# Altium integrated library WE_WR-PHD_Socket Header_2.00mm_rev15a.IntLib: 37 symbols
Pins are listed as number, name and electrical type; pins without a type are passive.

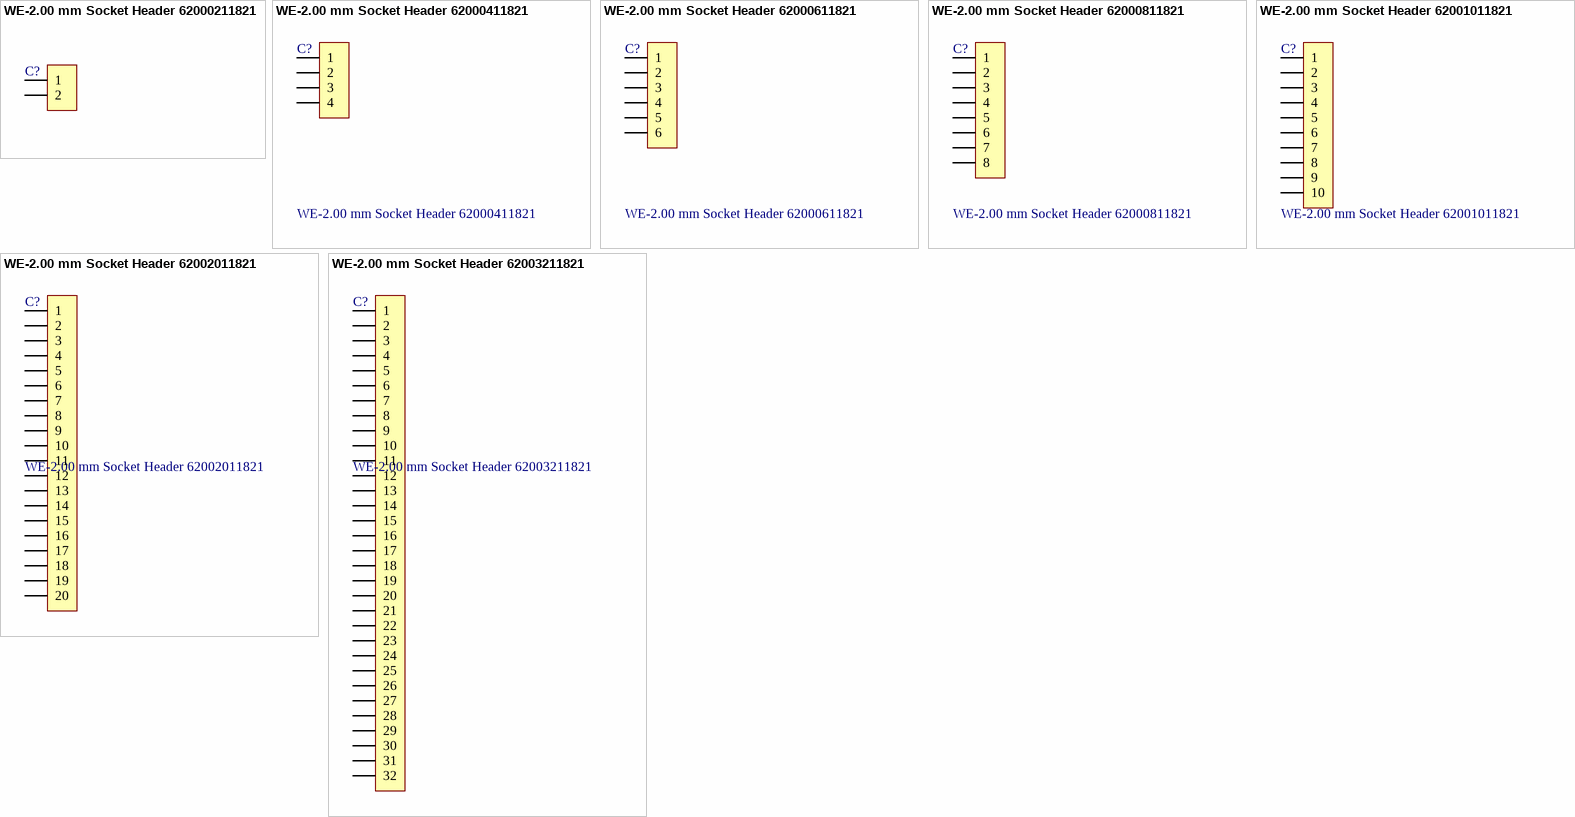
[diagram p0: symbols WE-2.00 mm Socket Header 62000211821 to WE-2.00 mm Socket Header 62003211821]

## WE-2.00 mm Socket Header 62000211821
designator C?
WR-PHD 2.00 mm Socket Header; Manufacturer: Würth Elektronik eiSos GmbH; ComponentLink1 Description: Manufacturer; ComponentLink2 Description: Datasheet; NoPins: 02
footprint 62000211821 (2p, 1 row, straight, gold plating)
pins: 1, 2

## WE-2.00 mm Socket Header 62000411821
designator C?
WR-PHD 2.00 mm Socket Header; Manufacturer: Würth Elektronik eiSos GmbH; ComponentLink1 Description: Manufacturer; ComponentLink2 Description: Datasheet; NoPins: 04
footprint 62000411821 (4p, 1 row, straight, gold plating)
pins: 1, 2, 3, 4

## WE-2.00 mm Socket Header 62000611821
designator C?
WR-PHD 2.00 mm Socket Header; Manufacturer: Würth Elektronik eiSos GmbH; ComponentLink1 Description: Manufacturer; ComponentLink2 Description: Datasheet; NoPins: 06
footprint 62000611821 (6p, 1 row, straight, gold plating)
pins: 1, 2, 3, 4, 5, 6

## WE-2.00 mm Socket Header 62000811821
designator C?
WR-PHD 2.00 mm Socket Header; Manufacturer: Würth Elektronik eiSos GmbH; ComponentLink1 Description: Manufacturer; ComponentLink2 Description: Datasheet; NoPins: 08
footprint 62000811821 (8p, 1 row, straight, gold plating)
pins: 1, 2, 3, 4, 5, 6, 7, 8

## WE-2.00 mm Socket Header 62001011821
designator C?
WR-PHD 2.00 mm Socket Header; Manufacturer: Würth Elektronik eiSos GmbH; ComponentLink1 Description: Manufacturer; ComponentLink2 Description: Datasheet; NoPins: 10
footprint 62001011821 (10p, 1 row, straight, gold plating)
pins: 1, 2, 3, 4, 5, 6, 7, 8, 9, 10

## WE-2.00 mm Socket Header 62002011821
designator C?
WR-PHD 2.00 mm Socket Header; Manufacturer: Würth Elektronik eiSos GmbH; ComponentLink1 Description: Manufacturer; ComponentLink2 Description: Datasheet; NoPins: 20
footprint 62002011821 (20p, 1 row, straight, gold plating)
pins: 1, 2, 3, 4, 5, 6, 7, 8, 9, 10, 11, 12, 13, 14, 15, 16, 17, 18, 19, 20

## WE-2.00 mm Socket Header 62003211821
designator C?
WR-PHD 2.00 mm Socket Header; Manufacturer: Würth Elektronik eiSos GmbH; ComponentLink1 Description: Manufacturer; ComponentLink2 Description: Datasheet; NoPins: 32
footprint 62003211821 (32p, 1 row, straight, gold plating)
pins: 1, 2, 3, 4, 5, 6, 7, 8, 9, 10, 11, 12, 13, 14, 15, 16, 17, 18, 19, 20, 21, 22, 23, 24, 25, 26, 27, 28, 29, 30, 31, 32


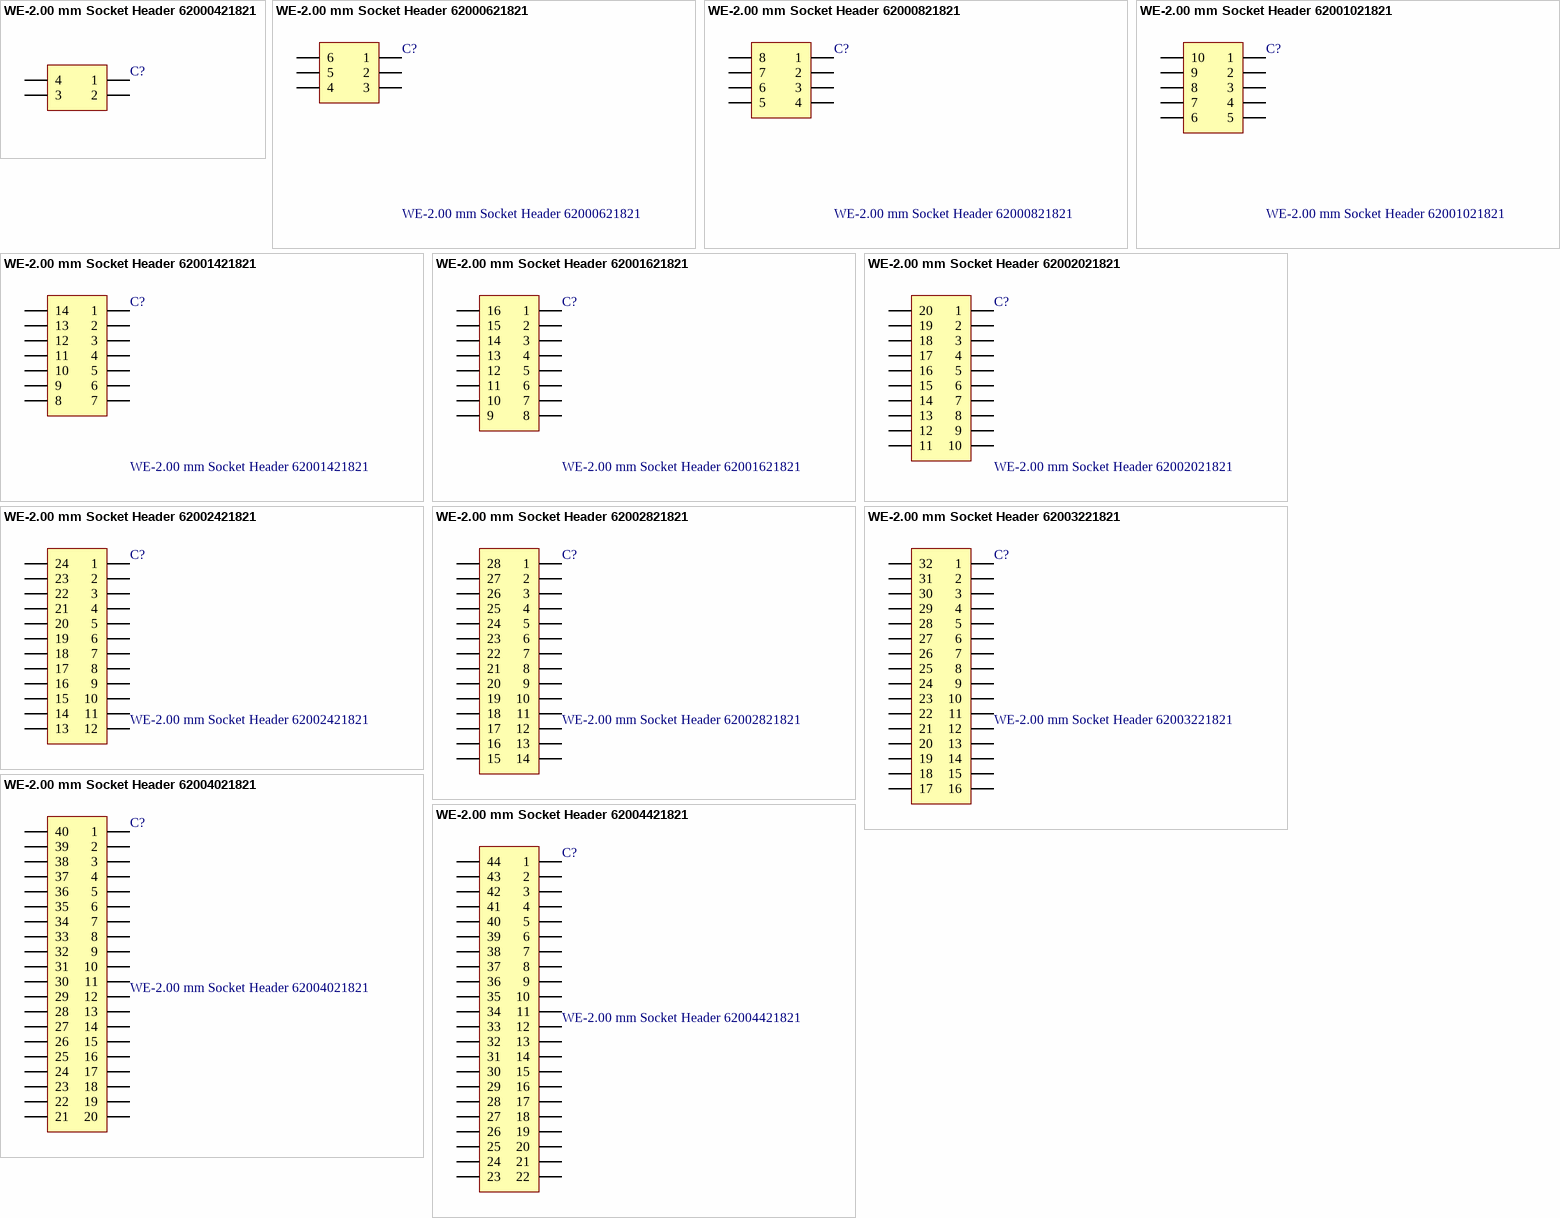
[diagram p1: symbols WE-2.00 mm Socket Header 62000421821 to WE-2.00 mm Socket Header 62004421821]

## WE-2.00 mm Socket Header 62000421821
designator C?
WR-PHD 2.00 mm Dual Socket Header; Manufacturer: Würth Elektronik eiSos GmbH; ComponentLink1 Description: Manufacturer; ComponentLink2 Description: Datasheet; NoPins: 04
footprint 62000421821 (4 pins, dual row, straight, gold plating)
pins: 1, 2, 3, 4

## WE-2.00 mm Socket Header 62000621821
designator C?
WR-PHD 2.00 mm Dual Socket Header; Manufacturer: Würth Elektronik eiSos GmbH; ComponentLink1 Description: Manufacturer; ComponentLink2 Description: Datasheet; NoPins: 06
footprint 62000621821 (6 pins, dual row, straight, gold plating)
pins: 1, 2, 3, 4, 5, 6

## WE-2.00 mm Socket Header 62000821821
designator C?
WR-PHD 2.00 mm Dual Socket Header; Manufacturer: Würth Elektronik eiSos GmbH; ComponentLink1 Description: Manufacturer; ComponentLink2 Description: Datasheet; NoPins: 08
footprint 62000821821 (8 pins, dual row, straight, gold plating)
pins: 1, 2, 3, 4, 5, 6, 7, 8

## WE-2.00 mm Socket Header 62001021821
designator C?
WR-PHD 2.00 mm Dual Socket Header; Manufacturer: Würth Elektronik eiSos GmbH; ComponentLink1 Description: Manufacturer; ComponentLink2 Description: Datasheet; NoPins: 10
footprint 62001021821 (10 pins, dual row, straight, gold plating)
pins: 1, 2, 3, 4, 5, 6, 7, 8, 9, 10

## WE-2.00 mm Socket Header 62001421821
designator C?
WR-PHD 2.00 mm Dual Socket Header; Manufacturer: Würth Elektronik eiSos GmbH; ComponentLink1 Description: Manufacturer; ComponentLink2 Description: Datasheet; NoPins: 14
footprint 62001421821 (14 pins, dual row, straight, gold plating)
pins: 1, 2, 3, 4, 5, 6, 7, 8, 9, 10, 11, 12, 13, 14

## WE-2.00 mm Socket Header 62001621821
designator C?
WR-PHD 2.00 mm Dual Socket Header; Manufacturer: Würth Elektronik eiSos GmbH; ComponentLink1 Description: Manufacturer; ComponentLink2 Description: Datasheet; NoPins: 16
footprint 62001621821 (16 pins, dual row, straight, gold plating)
pins: 1, 2, 3, 4, 5, 6, 7, 8, 9, 10, 11, 12, 13, 14, 15, 16

## WE-2.00 mm Socket Header 62002021821
designator C?
WR-PHD 2.00 mm Dual Socket Header; Manufacturer: Würth Elektronik eiSos GmbH; ComponentLink1 Description: Manufacturer; ComponentLink2 Description: Datasheet; NoPins: 20
footprint 62002021821 (20 pins, dual row, straight, gold plating)
pins: 1, 2, 3, 4, 5, 6, 7, 8, 9, 10, 11, 12, 13, 14, 15, 16, 17, 18, 19, 20

## WE-2.00 mm Socket Header 62002421821
designator C?
WR-PHD 2.00 mm Dual Socket Header; Manufacturer: Würth Elektronik eiSos GmbH; ComponentLink1 Description: Manufacturer; ComponentLink2 Description: Datasheet; NoPins: 24
footprint 62002421821 (24 pins, dual row, straight, gold plating)
pins: 1, 2, 3, 4, 5, 6, 7, 8, 9, 10, 11, 12, 13, 14, 15, 16, 17, 18, 19, 20, 21, 22, 23, 24

## WE-2.00 mm Socket Header 62002821821
designator C?
WR-PHD 2.00 mm Dual Socket Header; Manufacturer: Würth Elektronik eiSos GmbH; ComponentLink1 Description: Manufacturer; ComponentLink2 Description: Datasheet; NoPins: 28
footprint 62002821821 (28 pins, dual row, straight, gold plating)
pins: 1, 2, 3, 4, 5, 6, 7, 8, 9, 10, 11, 12, 13, 14, 15, 16, 17, 18, 19, 20, 21, 22, 23, 24, 25, 26, 27, 28

## WE-2.00 mm Socket Header 62003221821
designator C?
WR-PHD 2.00 mm Dual Socket Header; Manufacturer: Würth Elektronik eiSos GmbH; ComponentLink1 Description: Manufacturer; ComponentLink2 Description: Datasheet; NoPins: 32
footprint 62003221821 (32 pins, dual row, straight, gold plating)
pins: 1, 2, 3, 4, 5, 6, 7, 8, 9, 10, 11, 12, 13, 14, 15, 16, 17, 18, 19, 20, 21, 22, 23, 24, 25, 26, 27, 28, 29, 30, 31, 32

## WE-2.00 mm Socket Header 62004021821
designator C?
WR-PHD 2.00 mm Dual Socket Header; Manufacturer: Würth Elektronik eiSos GmbH; ComponentLink1 Description: Manufacturer; ComponentLink2 Description: Datasheet; NoPins: 40
footprint 62004021821 (40 pins, dual row, straight, gold plating)
pins: 1, 2, 3, 4, 5, 6, 7, 8, 9, 10, 11, 12, 13, 14, 15, 16, 17, 18, 19, 20, 21, 22, 23, 24, 25, 26, 27, 28, 29, 30, 31, 32, 33, 34, 35, 36, 37, 38, 39, 40

## WE-2.00 mm Socket Header 62004421821
designator C?
WR-PHD 2.00 mm Dual Socket Header; Manufacturer: Würth Elektronik eiSos GmbH; ComponentLink1 Description: Manufacturer; ComponentLink2 Description: Datasheet; NoPins: 44
footprint 62004421821 (44 pins, dual row, straight, gold plating)
pins: 1, 2, 3, 4, 5, 6, 7, 8, 9, 10, 11, 12, 13, 14, 15, 16, 17, 18, 19, 20, 21, 22, 23, 24, 25, 26, 27, 28, 29, 30, 31, 32, 33, 34, 35, 36, 37, 38, 39, 40, 41, 42, 43, 44


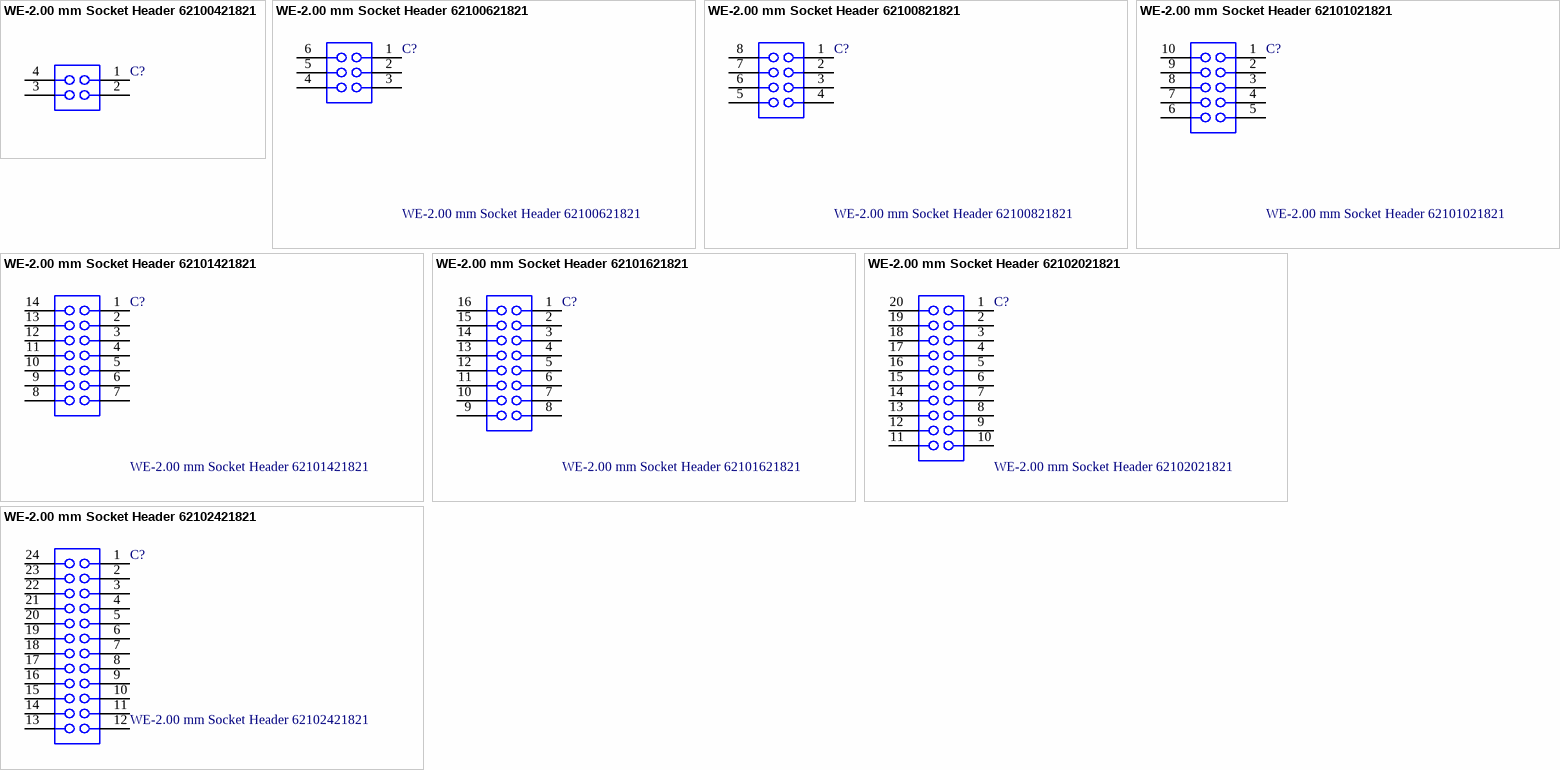
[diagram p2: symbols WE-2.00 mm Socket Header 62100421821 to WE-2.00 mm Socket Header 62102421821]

## WE-2.00 mm Socket Header 62100421821
designator C?
WR-PHD 2.00 mm Dual SMT Socket Header; Manufacturer: Würth Elektronik eiSos GmbH; ComponentLink1 Description: Manufacturer; ComponentLink2 Description: Datasheet; NoPins: 04
footprint 62100421821 (4 pins, dual row, straight, gold plating)
pins: 1, 2, 3, 4

## WE-2.00 mm Socket Header 62100621821
designator C?
WR-PHD 2.00 mm Dual SMT Socket Header; Manufacturer: Würth Elektronik eiSos GmbH; ComponentLink1 Description: Manufacturer; ComponentLink2 Description: Datasheet; NoPins: 06
footprint 62100621821 (6 pins, dual row, straight, gold plating)
pins: 1, 2, 3, 4, 5, 6

## WE-2.00 mm Socket Header 62100821821
designator C?
WR-PHD 2.00 mm Dual SMT Socket Header; Manufacturer: Würth Elektronik eiSos GmbH; ComponentLink1 Description: Manufacturer; ComponentLink2 Description: Datasheet; NoPins: 08
footprint 62100821821 (8 pins, dual row, straight, gold plating)
pins: 1, 2, 3, 4, 5, 6, 7, 8

## WE-2.00 mm Socket Header 62101021821
designator C?
WR-PHD 2.00 mm Dual SMT Socket Header; Manufacturer: Würth Elektronik eiSos GmbH; ComponentLink1 Description: Manufacturer; ComponentLink2 Description: Datasheet; NoPins: 10
footprint 62101021821 (10 pins, dual row, straight, gold plating)
pins: 1, 2, 3, 4, 5, 6, 7, 8, 9, 10

## WE-2.00 mm Socket Header 62101421821
designator C?
WR-PHD 2.00 mm Dual SMT Socket Header; Manufacturer: Würth Elektronik eiSos GmbH; ComponentLink1 Description: Manufacturer; ComponentLink2 Description: Datasheet; NoPins: 14
footprint 62101421821 (14 pins, dual row, straight, gold plating)
pins: 1, 2, 3, 4, 5, 6, 7, 8, 9, 10, 11, 12, 13, 14

## WE-2.00 mm Socket Header 62101621821
designator C?
WR-PHD 2.00 mm Dual SMT Socket Header; Manufacturer: Würth Elektronik eiSos GmbH; ComponentLink1 Description: Manufacturer; ComponentLink2 Description: Datasheet; NoPins: 16
footprint 62101621821 (16 pins, dual row, straight, gold plating)
pins: 1, 2, 3, 4, 5, 6, 7, 8, 9, 10, 11, 12, 13, 14, 15, 16

## WE-2.00 mm Socket Header 62102021821
designator C?
WR-PHD 2.00 mm Dual SMT Socket Header; Manufacturer: Würth Elektronik eiSos GmbH; ComponentLink1 Description: Manufacturer; ComponentLink2 Description: Datasheet; NoPins: 20
footprint 62102021821 (20 pins, dual row, straight, gold plating)
pins: 1, 2, 3, 4, 5, 6, 7, 8, 9, 10, 11, 12, 13, 14, 15, 16, 17, 18, 19, 20

## WE-2.00 mm Socket Header 62102421821
designator C?
WR-PHD 2.00 mm Dual SMT Socket Header; Manufacturer: Würth Elektronik eiSos GmbH; ComponentLink1 Description: Manufacturer; ComponentLink2 Description: Datasheet; NoPins: 24
footprint 62102421821 (24 pins, dual row, straight, gold plating)
pins: 1, 2, 3, 4, 5, 6, 7, 8, 9, 10, 11, 12, 13, 14, 15, 16, 17, 18, 19, 20, 21, 22, 23, 24


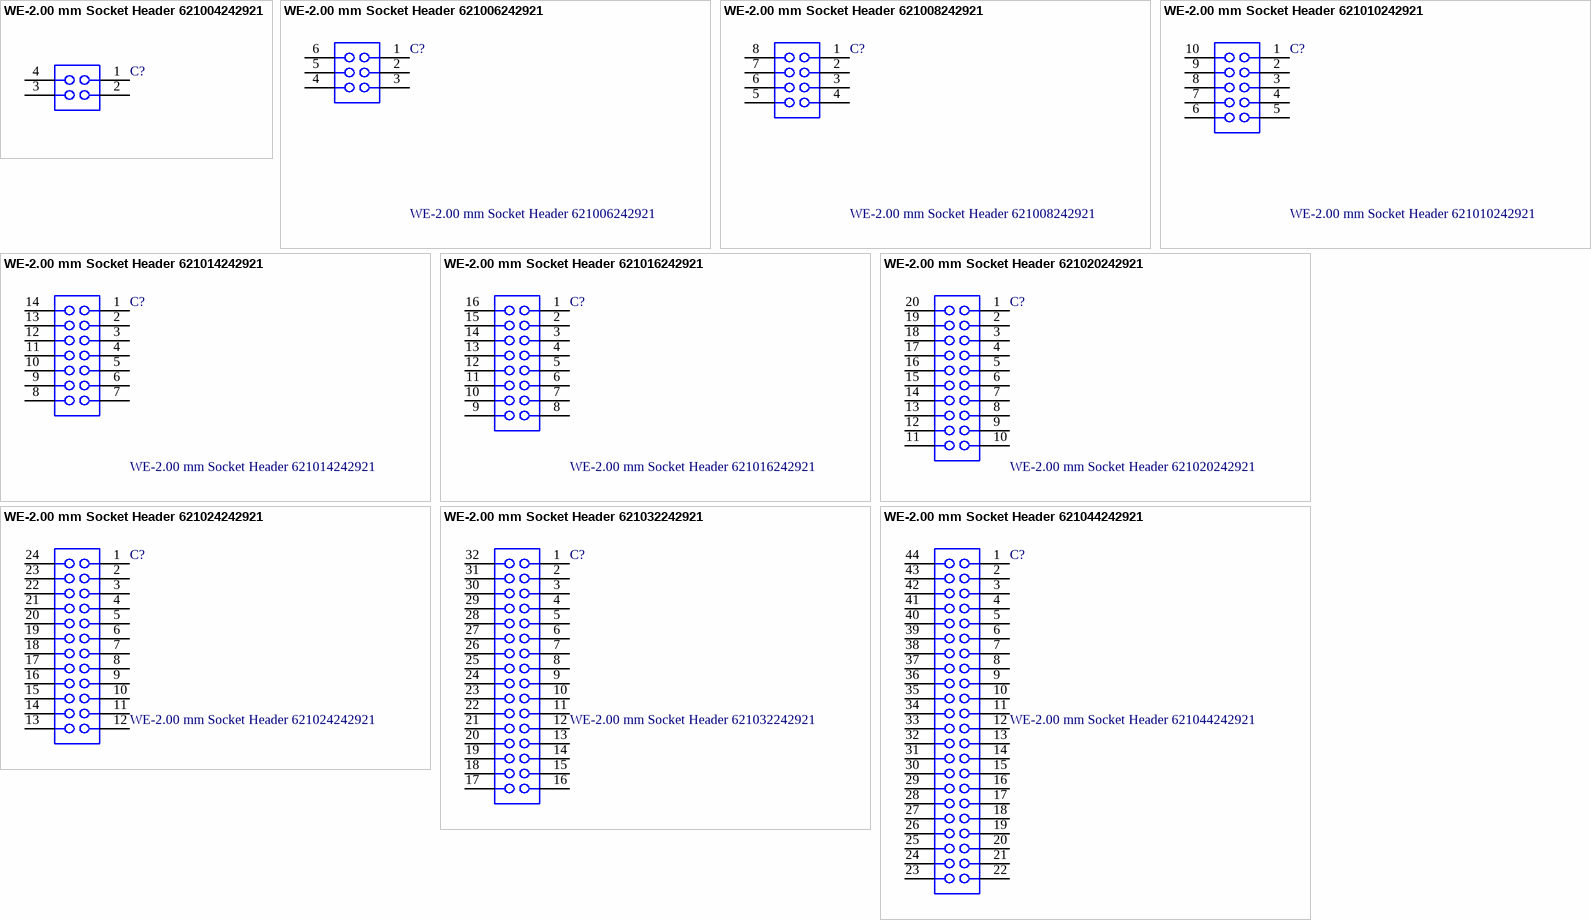
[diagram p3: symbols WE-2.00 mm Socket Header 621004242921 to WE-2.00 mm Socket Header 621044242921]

## WE-2.00 mm Socket Header 621004242921
designator C?
WR-PHD 2.00 mm Dual SMT Socket Header; Manufacturer: Würth Elektronik eiSos GmbH; ComponentLink1 Description: Manufacturer; ComponentLink2 Description: Datasheet; NoPins: 04
footprint 621004242921 (04p dual row straight 4,5mm height)
pins: 1, 2, 3, 4

## WE-2.00 mm Socket Header 621006242921
designator C?
WR-PHD 2.00 mm Dual SMT Socket Header; Manufacturer: Würth Elektronik eiSos GmbH; ComponentLink1 Description: Manufacturer; ComponentLink2 Description: Datasheet; NoPins: 06
footprint 621006242921 (06p dual row straight 4,5mm height)
pins: 1, 2, 3, 4, 5, 6

## WE-2.00 mm Socket Header 621008242921
designator C?
WR-PHD 2.00 mm Dual SMT Socket Header; Manufacturer: Würth Elektronik eiSos GmbH; ComponentLink1 Description: Manufacturer; ComponentLink2 Description: Datasheet; NoPins: 08
footprint 621008242921 (08p dual row straight 4,5mm height)
pins: 1, 2, 3, 4, 5, 6, 7, 8

## WE-2.00 mm Socket Header 621010242921
designator C?
WR-PHD 2.00 mm Dual SMT Socket Header; Manufacturer: Würth Elektronik eiSos GmbH; ComponentLink1 Description: Manufacturer; ComponentLink2 Description: Datasheet; NoPins: 10
footprint 621010242921 (10p dual row straight 4,5mm height)
pins: 1, 2, 3, 4, 5, 6, 7, 8, 9, 10

## WE-2.00 mm Socket Header 621014242921
designator C?
WR-PHD 2.00 mm Dual SMT Socket Header; Manufacturer: Würth Elektronik eiSos GmbH; ComponentLink1 Description: Manufacturer; ComponentLink2 Description: Datasheet; NoPins: 14
footprint 621014242921 (14p dual row straight 4,5mm height)
pins: 1, 2, 3, 4, 5, 6, 7, 8, 9, 10, 11, 12, 13, 14

## WE-2.00 mm Socket Header 621016242921
designator C?
WR-PHD 2.00 mm Dual SMT Socket Header; Manufacturer: Würth Elektronik eiSos GmbH; ComponentLink1 Description: Manufacturer; ComponentLink2 Description: Datasheet; NoPins: 16
footprint 621016242921 (16p dual row straight 4,5mm height)
pins: 1, 2, 3, 4, 5, 6, 7, 8, 9, 10, 11, 12, 13, 14, 15, 16

## WE-2.00 mm Socket Header 621020242921
designator C?
WR-PHD 2.00 mm Dual SMT Socket Header; Manufacturer: Würth Elektronik eiSos GmbH; ComponentLink1 Description: Manufacturer; ComponentLink2 Description: Datasheet; NoPins: 20
footprint 621020242921 (20p dual row straight 4,5mm height)
pins: 1, 2, 3, 4, 5, 6, 7, 8, 9, 10, 11, 12, 13, 14, 15, 16, 17, 18, 19, 20

## WE-2.00 mm Socket Header 621024242921
designator C?
WR-PHD 2.00 mm Dual SMT Socket Header; Manufacturer: Würth Elektronik eiSos GmbH; ComponentLink1 Description: Manufacturer; ComponentLink2 Description: Datasheet; NoPins: 24
footprint 621024242921 (24p dual row straight 4,5mm height)
pins: 1, 2, 3, 4, 5, 6, 7, 8, 9, 10, 11, 12, 13, 14, 15, 16, 17, 18, 19, 20, 21, 22, 23, 24

## WE-2.00 mm Socket Header 621032242921
designator C?
WR-PHD 2.00 mm Dual SMT Socket Header; Manufacturer: Würth Elektronik eiSos GmbH; ComponentLink1 Description: Manufacturer; ComponentLink2 Description: Datasheet; NoPins: 32
footprint 621032242921 (32p dual row straight 4,5mm height)
pins: 1, 2, 3, 4, 5, 6, 7, 8, 9, 10, 11, 12, 13, 14, 15, 16, 17, 18, 19, 20, 21, 22, 23, 24, 25, 26, 27, 28, 29, 30, 31, 32

## WE-2.00 mm Socket Header 621044242921
designator C?
WR-PHD 2.00 mm Dual SMT Socket Header; Manufacturer: Würth Elektronik eiSos GmbH; ComponentLink1 Description: Manufacturer; ComponentLink2 Description: Datasheet; NoPins: 44
footprint 621044242921 (44p dual row straight 4,5mm height)
pins: 1, 2, 3, 4, 5, 6, 7, 8, 9, 10, 11, 12, 13, 14, 15, 16, 17, 18, 19, 20, 21, 22, 23, 24, 25, 26, 27, 28, 29, 30, 31, 32, 33, 34, 35, 36, 37, 38, 39, 40, 41, 42, 43, 44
